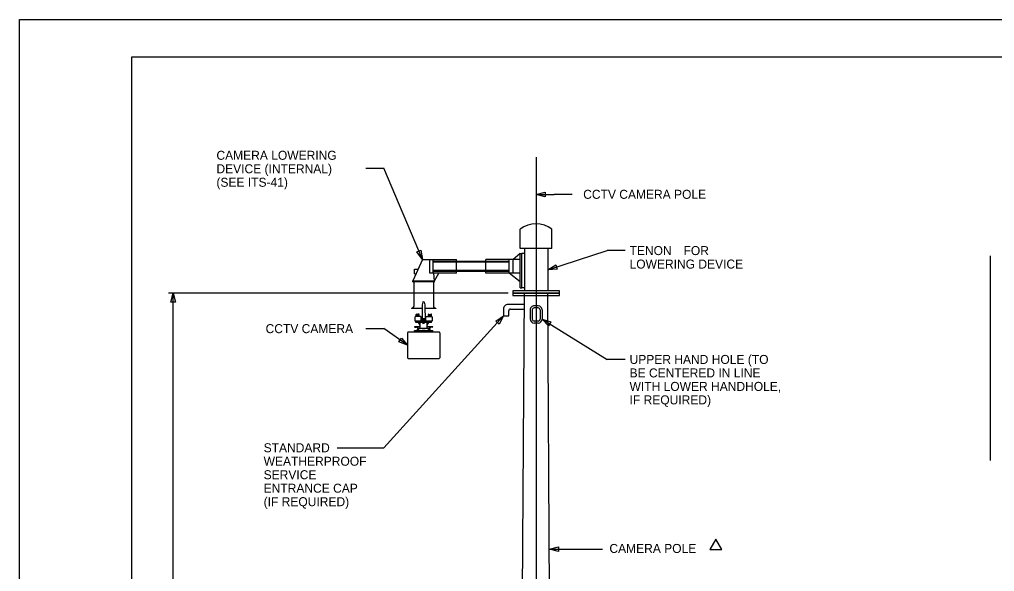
# Model space of a CAD drawing. Extents: x 1299104.7 to 1299141.5, y 239689.9 to 239711.9.
# Drawn here: x 1299104.72 to 1299117.74, y 239704.52 to 239711.89 of the extents above; entities that cross this region are included whole.
import ezdxf

# ---------------------------------------------------------------- set-up
doc = ezdxf.new("R2010")
doc.units = 0
for name, color, linetype in [('DIM TXT', 7, 'Continuous'), ('GS_plotshape_p', 7, 'Continuous'), ('Level 1', 7, 'Continuous'), ('Level 3', 7, 'Continuous'), ('Level 7', 7, 'Continuous'), ('Level 8', 7, 'Continuous')]:
    doc.layers.add(name, color=color, linetype=linetype)

msp = doc.modelspace()

# ---------------------------------------------------------------- linework, layer by layer
at = {"layer": 'DIM TXT'}
msp.add_line((1299104.722, 239711.886), (1299104.722, 239711.886), dxfattribs=at)
msp.add_lwpolyline([(1299113.936, 239704.809), (1299114.098, 239704.809), (1299114.017, 239704.95)], close=True, dxfattribs=at)
at = {"layer": 'GS_plotshape_p'}
msp.add_lwpolyline([(1299104.722, 239711.886), (1299138.722, 239711.886), (1299138.722, 239689.886), (1299104.722, 239689.886)], close=True, dxfattribs=at)
at = {"layer": 'Level 1'}
msp.add_lwpolyline([(1299138.222, 239690.386), (1299106.222, 239690.386), (1299106.222, 239711.386), (1299138.222, 239711.386)], close=True, dxfattribs=at)
at = {"layer": 'Level 3'}
for p, q in [((1299111.407, 239708.828), (1299111.407, 239709.087)), ((1299111.829, 239708.828), (1299111.829, 239709.087)), ((1299111.829, 239708.828), (1299111.407, 239708.828)), ((1299111.462, 239708.828), (1299111.462, 239708.262)), ((1299111.774, 239708.828), (1299111.774, 239708.262)), ((1299111.404, 239708.761), (1299111.31, 239708.684)), ((1299111.404, 239708.305), (1299111.404, 239708.761)), ((1299111.404, 239708.761), (1299111.428, 239708.761)), ((1299111.428, 239708.305), (1299111.428, 239708.761)), ((1299111.462, 239708.761), (1299111.428, 239708.761)), ((1299117.68, 239708.733), (1299117.68, 239706)), ((1299110.1, 239708.684), (1299109.973, 239708.396)), ((1299110.1, 239708.684), (1299110.556, 239708.684)), ((1299110.199, 239708.499), (1299110.199, 239708.684)), ((1299110.245, 239708.499), (1299110.245, 239708.684)), ((1299110.245, 239708.661), (1299110.556, 239708.661)), ((1299110.245, 239708.649), (1299110.556, 239708.649)), ((1299110.556, 239708.661), (1299110.556, 239708.684)), ((1299110.556, 239708.499), (1299110.556, 239708.661)), ((1299110.556, 239708.661), (1299110.948, 239708.661)), ((1299110.556, 239708.649), (1299110.948, 239708.649)), ((1299111.404, 239708.684), (1299110.948, 239708.684)), ((1299110.948, 239708.499), (1299110.948, 239708.684)), ((1299110.948, 239708.661), (1299111.259, 239708.661)), ((1299110.948, 239708.649), (1299111.259, 239708.649)), ((1299111.259, 239708.499), (1299111.259, 239708.684)), ((1299111.31, 239708.499), (1299111.31, 239708.684)), ((1299109.995, 239708.491), (1299109.995, 239708.555)), ((1299109.995, 239708.491), (1299110.015, 239708.491)), ((1299109.996, 239708.554), (1299110.043, 239708.554)), ((1299110.556, 239708.499), (1299110.199, 239708.499)), ((1299110.245, 239708.54), (1299110.556, 239708.54)), ((1299110.245, 239708.527), (1299110.556, 239708.527)), ((1299110.26, 239708.396), (1299110.253, 239708.499)), ((1299110.26, 239708.396), (1299110.321, 239708.499)), ((1299110.324, 239708.527), (1299110.352, 239708.527)), ((1299110.479, 239708.527), (1299110.507, 239708.527)), ((1299110.556, 239708.54), (1299110.948, 239708.54)), ((1299110.556, 239708.527), (1299110.948, 239708.527)), ((1299110.948, 239708.54), (1299111.259, 239708.54)), ((1299110.948, 239708.527), (1299111.259, 239708.527)), ((1299111.259, 239708.499), (1299110.948, 239708.499)), ((1299110.998, 239708.499), (1299110.948, 239708.499)), ((1299110.998, 239708.527), (1299111.026, 239708.527)), ((1299111.152, 239708.527), (1299111.18, 239708.527)), ((1299111.404, 239708.499), (1299111.18, 239708.499)), ((1299111.404, 239708.385), (1299111.259, 239708.499)), ((1299109.973, 239708.396), (1299110.26, 239708.396)), ((1299109.973, 239708.385), (1299109.973, 239708.396)), ((1299110.26, 239708.385), (1299109.973, 239708.385)), ((1299109.973, 239708.385), (1299109.978, 239708.385)), ((1299109.988, 239708.391), (1299109.978, 239708.391)), ((1299109.978, 239708.385), (1299109.978, 239708.391)), ((1299109.984, 239708.385), (1299109.984, 239708.058)), ((1299110.249, 239708.385), (1299109.984, 239708.385)), ((1299109.986, 239708.385), (1299109.986, 239708.055)), ((1299109.988, 239708.385), (1299109.988, 239708.391)), ((1299110.244, 239708.391), (1299110.255, 239708.391)), ((1299110.244, 239708.385), (1299110.244, 239708.391)), ((1299110.246, 239708.385), (1299110.246, 239708.055)), ((1299110.249, 239708.385), (1299110.249, 239708.058)), ((1299110.255, 239708.385), (1299110.255, 239708.391)), ((1299110.255, 239708.385), (1299110.26, 239708.385)), ((1299110.26, 239708.385), (1299110.26, 239708.396)), ((1299111.404, 239708.305), (1299111.428, 239708.305)), ((1299111.462, 239708.305), (1299111.428, 239708.305)), ((1299111.424, 239701.856), (1299111.462, 239708.231)), ((1299111.812, 239701.856), (1299111.774, 239708.231)), ((1299110.099, 239708.075), (1299110.095, 239707.859)), ((1299110.107, 239708.114), (1299110.099, 239708.075)), ((1299110.109, 239708.116), (1299110.123, 239708.116)), ((1299110.125, 239708.114), (1299110.133, 239708.075)), ((1299110.133, 239708.075), (1299110.136, 239707.859)), ((1299111.645, 239708.063), (1299111.592, 239708.063)), ((1299109.953, 239708.032), (1299109.953, 239708.03)), ((1299110.098, 239708.03), (1299109.953, 239708.03)), ((1299110, 239707.914), (1299110, 239707.864)), ((1299110.079, 239707.919), (1299110.005, 239707.919)), ((1299110.014, 239707.919), (1299110.014, 239707.924)), ((1299110.017, 239707.927), (1299110.017, 239707.95)), ((1299110.022, 239707.927), (1299110.017, 239707.927)), ((1299110.022, 239707.927), (1299110.022, 239707.95)), ((1299110.024, 239707.919), (1299110.024, 239707.924)), ((1299110.026, 239707.919), (1299110.026, 239707.924)), ((1299110.029, 239707.927), (1299110.029, 239707.95)), ((1299110.034, 239707.927), (1299110.029, 239707.927)), ((1299110.034, 239707.927), (1299110.034, 239707.95)), ((1299110.036, 239707.919), (1299110.036, 239707.924)), ((1299110.039, 239707.919), (1299110.039, 239707.924)), ((1299110.041, 239707.927), (1299110.041, 239707.95)), ((1299110.046, 239707.927), (1299110.041, 239707.927)), ((1299110.046, 239707.927), (1299110.046, 239707.95)), ((1299110.049, 239707.919), (1299110.049, 239707.924)), ((1299110.05, 239707.919), (1299110.05, 239707.924)), ((1299110.052, 239707.927), (1299110.052, 239707.95)), ((1299110.057, 239707.927), (1299110.052, 239707.927)), ((1299110.057, 239707.927), (1299110.057, 239707.95)), ((1299110.06, 239707.919), (1299110.06, 239707.924)), ((1299110.084, 239707.859), (1299110.084, 239707.914)), ((1299110.277, 239708.03), (1299110.133, 239708.03)), ((1299110.146, 239707.859), (1299110.146, 239707.914)), ((1299110.151, 239707.919), (1299110.158, 239707.919)), ((1299110.158, 239707.919), (1299110.225, 239707.919)), ((1299110.179, 239707.919), (1299110.179, 239707.924)), ((1299110.182, 239707.927), (1299110.182, 239707.95)), ((1299110.182, 239707.927), (1299110.187, 239707.927)), ((1299110.187, 239707.927), (1299110.187, 239707.95)), ((1299110.19, 239707.919), (1299110.19, 239707.924)), ((1299110.19, 239707.919), (1299110.19, 239707.924)), ((1299110.193, 239707.927), (1299110.193, 239707.95)), ((1299110.193, 239707.927), (1299110.198, 239707.927)), ((1299110.198, 239707.927), (1299110.198, 239707.95)), ((1299110.2, 239707.919), (1299110.2, 239707.924)), ((1299110.203, 239707.919), (1299110.203, 239707.924)), ((1299110.205, 239707.927), (1299110.205, 239707.95)), ((1299110.205, 239707.927), (1299110.21, 239707.927)), ((1299110.21, 239707.927), (1299110.21, 239707.95)), ((1299110.213, 239707.919), (1299110.213, 239707.924)), ((1299110.215, 239707.919), (1299110.215, 239707.924)), ((1299110.217, 239707.927), (1299110.217, 239707.95)), ((1299110.217, 239707.927), (1299110.222, 239707.927)), ((1299110.222, 239707.927), (1299110.222, 239707.95)), ((1299110.225, 239707.919), (1299110.225, 239707.924)), ((1299110.23, 239707.914), (1299110.23, 239707.864)), ((1299110.277, 239708.032), (1299110.277, 239708.03)), ((1299111.539, 239708.01), (1299111.539, 239707.887)), ((1299111.566, 239708.01), (1299111.566, 239707.887)), ((1299111.645, 239708.037), (1299111.592, 239708.037)), ((1299111.671, 239708.01), (1299111.671, 239707.887)), ((1299111.698, 239708.01), (1299111.698, 239707.887)), ((1299109.996, 239707.788), (1299109.993, 239707.786)), ((1299109.993, 239707.786), (1299109.997, 239707.782)), ((1299109.996, 239707.788), (1299110.069, 239707.788)), ((1299109.996, 239707.788), (1299109.998, 239707.786)), ((1299110, 239707.78), (1299110.018, 239707.78)), ((1299110.001, 239707.78), (1299110.001, 239707.784)), ((1299110.002, 239707.784), (1299110.019, 239707.784)), ((1299110.005, 239707.859), (1299110.034, 239707.859)), ((1299110.009, 239707.78), (1299110.009, 239707.784)), ((1299110.012, 239707.843), (1299110.012, 239707.859)), ((1299110.024, 239707.859), (1299110.012, 239707.859)), ((1299110.141, 239707.843), (1299110.012, 239707.843)), ((1299110.136, 239707.859), (1299110.026, 239707.859)), ((1299110.027, 239707.781), (1299110.04, 239707.766)), ((1299110.036, 239707.859), (1299110.084, 239707.859)), ((1299110.069, 239707.806), (1299110.046, 239707.843)), ((1299110.058, 239707.859), (1299110.058, 239707.843)), ((1299110.069, 239707.763), (1299110.069, 239707.843)), ((1299110.093, 239707.847), (1299110.093, 239707.856)), ((1299110.104, 239707.847), (1299110.104, 239707.856)), ((1299110.11, 239707.824), (1299110.11, 239707.9)), ((1299110.122, 239707.824), (1299110.122, 239707.9)), ((1299110.129, 239707.847), (1299110.129, 239707.856)), ((1299110.22, 239707.859), (1299110.136, 239707.859)), ((1299110.14, 239707.847), (1299110.14, 239707.856)), ((1299110.22, 239707.843), (1299110.141, 239707.843)), ((1299110.225, 239707.859), (1299110.146, 239707.859)), ((1299110.164, 239707.763), (1299110.164, 239707.843)), ((1299110.164, 239707.806), (1299110.186, 239707.843)), ((1299110.164, 239707.788), (1299110.236, 239707.788)), ((1299110.174, 239707.859), (1299110.174, 239707.843)), ((1299110.205, 239707.781), (1299110.192, 239707.766)), ((1299110.23, 239707.784), (1299110.213, 239707.784)), ((1299110.232, 239707.78), (1299110.214, 239707.78)), ((1299110.22, 239707.843), (1299110.22, 239707.859)), ((1299110.223, 239707.78), (1299110.223, 239707.784)), ((1299110.231, 239707.78), (1299110.231, 239707.784)), ((1299110.236, 239707.788), (1299110.234, 239707.786)), ((1299110.236, 239707.788), (1299110.239, 239707.786)), ((1299110.239, 239707.786), (1299110.236, 239707.782)), ((1299111.645, 239707.861), (1299111.592, 239707.861)), ((1299111.645, 239707.834), (1299111.592, 239707.834)), ((1299109.901, 239707.705), (1299109.901, 239707.37)), ((1299109.911, 239707.715), (1299110.322, 239707.715)), ((1299109.996, 239707.734), (1299110.237, 239707.734)), ((1299109.996, 239707.715), (1299109.996, 239707.734)), ((1299110.047, 239707.759), (1299110.022, 239707.734)), ((1299110.025, 239707.777), (1299110.038, 239707.763)), ((1299110.046, 239707.759), (1299110.069, 239707.759)), ((1299110.047, 239707.763), (1299110.069, 239707.763)), ((1299110.186, 239707.759), (1299110.047, 239707.759)), ((1299110.047, 239707.734), (1299110.047, 239707.759)), ((1299110.054, 239707.759), (1299110.054, 239707.763)), ((1299110.069, 239707.759), (1299110.069, 239707.763)), ((1299110.097, 239707.759), (1299110.097, 239707.763)), ((1299110.097, 239707.759), (1299110.136, 239707.759)), ((1299110.114, 239707.759), (1299110.114, 239707.763)), ((1299110.119, 239707.759), (1299110.119, 239707.763)), ((1299110.135, 239707.759), (1299110.135, 239707.763)), ((1299110.164, 239707.759), (1299110.164, 239707.763)), ((1299110.164, 239707.763), (1299110.185, 239707.763)), ((1299110.164, 239707.759), (1299110.186, 239707.759)), ((1299110.178, 239707.759), (1299110.178, 239707.763)), ((1299110.186, 239707.734), (1299110.186, 239707.759)), ((1299110.186, 239707.759), (1299110.212, 239707.734)), ((1299110.207, 239707.777), (1299110.194, 239707.763)), ((1299110.237, 239707.715), (1299110.237, 239707.734)), ((1299110.332, 239707.705), (1299110.332, 239707.37)), ((1299109.911, 239707.36), (1299110.322, 239707.36))]:
    msp.add_line(p, q, dxfattribs=at)
for points in [[(1299111.931, 239708.262), (1299111.306, 239708.262), (1299111.306, 239708.231), (1299111.931, 239708.231)], [(1299111.931, 239708.231), (1299111.306, 239708.231), (1299111.306, 239708.2), (1299111.931, 239708.2)]]:
    msp.add_lwpolyline(points, close=True, dxfattribs=at)
for points in [[(1299111.461, 239708.082), (1299111.243, 239708.082)], [(1299111.181, 239708.02), (1299111.181, 239707.929), (1299111.254, 239707.929), (1299111.254, 239707.998)], [(1299111.274, 239708.018), (1299111.461, 239708.018)]]:
    msp.add_lwpolyline(points, dxfattribs=at)
for centre, radius, start, end in [((1299111.618, 239708.82), 0.34, 51.5919, 128.4081), ((1299109.956, 239708.06), 0.0275, 265.7636, 355.7636), ((1299109.957, 239708.058), 0.0287, 295.1294, 353.6013), ((1299110.109, 239708.113), 0.00254, 90, 168.1745), ((1299110.123, 239708.113), 0.00254, 11.8255, 90), ((1299110.275, 239708.058), 0.0284, 186.1305, 245.4585), ((1299110.276, 239708.06), 0.0273, 184.1096, 269.764), ((1299111.243, 239708.02), 0.0621, 90.0001, 180.0001), ((1299111.592, 239708.01), 0.0528, 89.9999, 179.9999), ((1299111.645, 239708.01), 0.0528, 359.9999, 89.9999), ((1299110.005, 239707.914), 0.00507, 90, 180), ((1299110.017, 239707.924), 0.00254, 90, 180), ((1299110.019, 239707.95), 0.00254, 0, 180), ((1299110.022, 239707.924), 0.00254, 0, 90), ((1299110.029, 239707.924), 0.00254, 90, 180), ((1299110.031, 239707.95), 0.00254, 0, 180), ((1299110.034, 239707.924), 0.00254, 0, 90), ((1299110.041, 239707.924), 0.00254, 90, 180), ((1299110.044, 239707.95), 0.00254, 0, 180), ((1299110.046, 239707.924), 0.00254, 0, 90), ((1299110.052, 239707.924), 0.00254, 90, 180), ((1299110.055, 239707.95), 0.00254, 0, 180), ((1299110.057, 239707.924), 0.00254, 0, 90), ((1299110.079, 239707.914), 0.00507, 0, 90), ((1299110.151, 239707.914), 0.00507, 90, 180), ((1299110.182, 239707.924), 0.00254, 90, 180), ((1299110.184, 239707.95), 0.00254, 0, 180), ((1299110.187, 239707.924), 0.00254, 0, 90), ((1299110.193, 239707.924), 0.00254, 90, 180), ((1299110.195, 239707.95), 0.00254, 0, 180), ((1299110.198, 239707.924), 0.00254, 0, 90), ((1299110.205, 239707.924), 0.00254, 90, 180), ((1299110.208, 239707.95), 0.00254, 0, 180), ((1299110.21, 239707.924), 0.00254, 0, 90), ((1299110.217, 239707.924), 0.00254, 90, 180), ((1299110.22, 239707.95), 0.00254, 0, 180), ((1299110.222, 239707.924), 0.00254, 0, 90), ((1299110.225, 239707.914), 0.00507, 0, 90), ((1299111.274, 239707.998), 0.0207, 90.0001, 180.0001), ((1299111.592, 239708.01), 0.0264, 89.9999, 179.9999), ((1299111.645, 239708.01), 0.0264, 359.9999, 89.9999), ((1299110, 239707.785), 0.00507, 222.0892, 270), ((1299110.002, 239707.789), 0.00507, 222.0892, 270), ((1299110.005, 239707.864), 0.00507, 180, 269.7176), ((1299110.018, 239707.77), 0.0101, 42.1014, 90), ((1299110.019, 239707.774), 0.0101, 42.1014, 90), ((1299110.213, 239707.774), 0.0101, 90, 137.8986), ((1299110.214, 239707.77), 0.0101, 90, 137.8986), ((1299110.225, 239707.864), 0.00507, 270.2824, 0), ((1299110.23, 239707.789), 0.00507, 270, 317.9108), ((1299110.232, 239707.785), 0.00507, 270, 317.9108), ((1299111.592, 239707.887), 0.0528, 179.9999, 269.9999), ((1299111.592, 239707.886), 0.0264, 179.9999, 269.9999), ((1299111.645, 239707.887), 0.0528, 269.9999, 359.9999), ((1299111.645, 239707.886), 0.0264, 269.9999, 359.9999), ((1299109.911, 239707.705), 0.0101, 90, 180), ((1299110.046, 239707.769), 0.0101, 222.1014, 270), ((1299110.047, 239707.773), 0.0101, 222.1014, 270), ((1299110.185, 239707.773), 0.0101, 270, 317.8986), ((1299110.186, 239707.769), 0.0101, 270, 317.8986), ((1299110.322, 239707.705), 0.0101, 0, 90), ((1299109.911, 239707.37), 0.0101, 180, 270), ((1299110.322, 239707.37), 0.0101, 270, 0)]:
    msp.add_arc(centre, radius, start, end, dxfattribs=at)
at = {"layer": 'Level 7'}
msp.add_line((1299111.618, 239710.05), (1299111.618, 239696.136), dxfattribs=at)
at = {"layer": 'Level 8'}
for p, q in [((1299109.346, 239709.899), (1299109.586, 239709.899)), ((1299110.1, 239708.684), (1299109.586, 239709.899)), ((1299111.618, 239709.55), (1299111.858, 239709.55)), ((1299112.098, 239709.55), (1299111.858, 239709.55)), ((1299111.774, 239708.545), (1299112.565, 239708.801)), ((1299112.805, 239708.801), (1299112.565, 239708.801)), ((1299111.246, 239708.231), (1299106.713, 239708.231)), ((1299106.773, 239697.356), (1299106.773, 239708.231)), ((1299111.181, 239707.929), (1299109.586, 239706.169)), ((1299111.698, 239707.887), (1299112.565, 239707.348)), ((1299109.346, 239707.759), (1299109.586, 239707.759)), ((1299109.901, 239707.537), (1299109.586, 239707.759)), ((1299112.805, 239707.348), (1299112.565, 239707.348)), ((1299108.961, 239706.169), (1299109.586, 239706.169)), ((1299111.795, 239704.816), (1299112.504, 239704.816))]:
    msp.add_line(p, q, dxfattribs=at)
for points in [[(1299111.738, 239709.52), (1299111.618, 239709.55), (1299111.738, 239709.58)], [(1299110.081, 239708.806), (1299110.1, 239708.684), (1299110.026, 239708.783)], [(1299111.898, 239708.554), (1299111.774, 239708.545), (1299111.879, 239708.611)], [(1299106.743, 239708.111), (1299106.773, 239708.231), (1299106.803, 239708.111)], [(1299111.078, 239707.861), (1299111.181, 239707.929), (1299111.123, 239707.82)], [(1299111.784, 239707.798), (1299111.698, 239707.887), (1299111.815, 239707.849)], [(1299109.82, 239707.631), (1299109.901, 239707.537), (1299109.786, 239707.582)], [(1299111.915, 239704.786), (1299111.795, 239704.816), (1299111.915, 239704.846)]]:
    msp.add_lwpolyline(points, close=True, dxfattribs=at)

# ---------------------------------------------------------------- texts
at = {"layer": 'DIM TXT'}
for s, p in [('CAMERA LOWERING', (1299107.351, 239710.013)), ('DEVICE (INTERNAL)', (1299107.351, 239709.833)), ('(SEE ITS-41)', (1299107.351, 239709.653)), ('  CCTV CAMERA POLE', (1299112.157, 239709.492)), ('TENON ', (1299112.865, 239708.741)), ('FOR', (1299113.585, 239708.741)), ('LOWERING DEVICE', (1299112.865, 239708.561)), ('CCTV CAMERA', (1299108.007, 239707.699)), ('UPPER HAND HOLE (TO', (1299112.865, 239707.288)), ('BE CENTERED IN LINE', (1299112.865, 239707.108)), ('WITH LOWER HANDHOLE,', (1299112.865, 239706.928)), ('IF REQUIRED)', (1299112.865, 239706.748)), ('STANDARD', (1299107.981, 239706.109)), ('WEATHERPROOF', (1299107.981, 239705.929)), ('SERVICE', (1299107.981, 239705.749)), ('ENTRANCE CAP', (1299107.981, 239705.569)), ('(IF REQUIRED)', (1299107.981, 239705.389)), ('CAMERA POLE', (1299112.596, 239704.765))]:
    msp.add_text(s, height=0.12, dxfattribs=at).set_placement(p)

doc.saveas('drawing.dxf')
